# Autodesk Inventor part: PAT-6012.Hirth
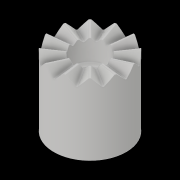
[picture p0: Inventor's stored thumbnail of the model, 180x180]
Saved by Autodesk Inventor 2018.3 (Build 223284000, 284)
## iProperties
Created: 2020-03
Part Number: PAT-6012.Hirth
Material: Generic
Document SubType Name: Modeling
Designer: Th. Mörgeli
Mass: 17.6441 g
Surface Area: 48.3626 cm^2
Volume: 17.6441 cm^3
Density: 1 g/cm^3
Appearance: Default
Author: Th. Mörgeli
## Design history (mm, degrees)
sketch "Sketch2"
  geometry: L1 (-7, 1.963)-(-7, -8); L2 (-7, -8)-(-6, -9); L3 (-6, -9)-(-6, -15); L4 (-6, -15)-(0, -17.184); L5 (0, -17.184)-(0, -28); L6 (0, -28)-(-15, -28); L7 (-15, -28)-(-15, 1.963); L8 (-15, 1.963)-(-7, 1.963); 1 further point
  constraints: 16 end point, 2 parallel, 2 perpendicular, 1 horizontal, 1 point on line, 1 vertical
  dimensions: "d8" = 14 diameter of L1 L5 (= Gewindebohrungsdurchmesser); "d10" = 12 diameter of L3 L5 (= Bohrungsdurchmesser); "d11" = 8 vertical distance of L1.end point (0, 0) (= Gewindetiefe); "d12" = 15 vertical distance of L3.end point (0, 0) (= Bohrungstiefe); "d14" = 45 deg angle of L1 L2; "d15" = 70 deg angle of L5 L4; "d16" = 1.9635 distance from line of point (0, 0) L8 (= 0.5 x Zahnhoehe); "d17" = 30 diameter of L7 L5 (= Aussendurchmesser); "d18" = 28 distance from line of point (0, 0) L6 (= Laenge)
revolve "Grundkoerper" sketch "Sketch2" stored, may be unused: angle "d19" = 90 deg
sketch "SKIZZE Ebene"
  geometry: L1 (-0.477, 0)-(-15, 0); L2 (-15, 0)-(-15, -1.963); L3 (-15, -1.963)-(-0.477, 0); L4 (-15, -1.963)-(-15.265, 0); 1 further point
  constraints: 8 end point, 2 perpendicular, 2 point on line, 1 horizontal
  dimensions: "d21" = 7.69944 deg angle of L1 L3 (= Neigungswinkel); "d34" = 15 distance of L1.end point (0, 0) (= 0.5 x Aussendurchmesser); "d35" = 0.47661 distance of point (0, 0) L1.start (= Offset)
node "EBENE"
sketch "Sketch4"
  geometry: L1 (-0.064, 0)-(7.79, 7.854); L2 (7.79, 7.854)-(7.79, -7.854); L3 (7.79, -7.854)-(-0.064, 0); L4 (-0.064, 0)-(7.79, 0)
  constraints: 8 end point, 1 midpoint, 1 perpendicular, 1 vertical, 1 other
  dimensions: "d23" = 90 deg angle of L1 L3 (= Flankenwinkel); "d24" = 7.85398 distance of L1.start L4.end (= 2 x Zahnhoehe)
extrude "Zahnluecke" cut sketch "Sketch4" extent not by distance; stored distance "d25" = 10; taper "d26" = 0 deg
fillet "Fussradius" dims "d27" = 0.5 (= Fussradius)
pattern_circular "MUSTER Zahn" dims angle "d29" = 360 deg
chamfer "Kopfspiel" distance "d31" = 0.49497 (= 0.707107 x Kopfflaeche); stored, may be unused: second distance "d32" = 2, angle "d33" = 45 deg
body "Solid2"
other parameters: "Aussendurchmesser" = 30 [user parameter; used in 4 equation terms], "Laenge" = 28 [user parameter; used in 1 equation term], "Gewindebohrungsdurchmesser" = 14 [user parameter; used in 1 equation term], "Gewindetiefe" = 8 [user parameter; used in 1 equation term], "Bohrungsdurchmesser" = 12 [user parameter; used in 1 equation term], "Bohrungstiefe" = 15 [user parameter; used in 1 equation term], "Zahnhoehe" = 22.5 deg (computed from Aussendurchmesser, Zaehnezahl, Flankenwinkel) [user parameter; used in 3 equation terms], "Neigungswinkel" = 7.69944 deg [user parameter; used in 2 equation terms], "d22" = 90 deg, "Flankenwinkel" = 90 deg [user parameter; used in 2 equation terms], "Fussradius" = 0.5 [user parameter; used in 1 equation term], "Kopfflaeche" = 0.7 [user parameter; used in 1 equation term], "Offset" = 0.47661 (computed from Aussendurchmesser, Neigungswinkel, Zahnhoehe) [user parameter; used in 1 equation term]
